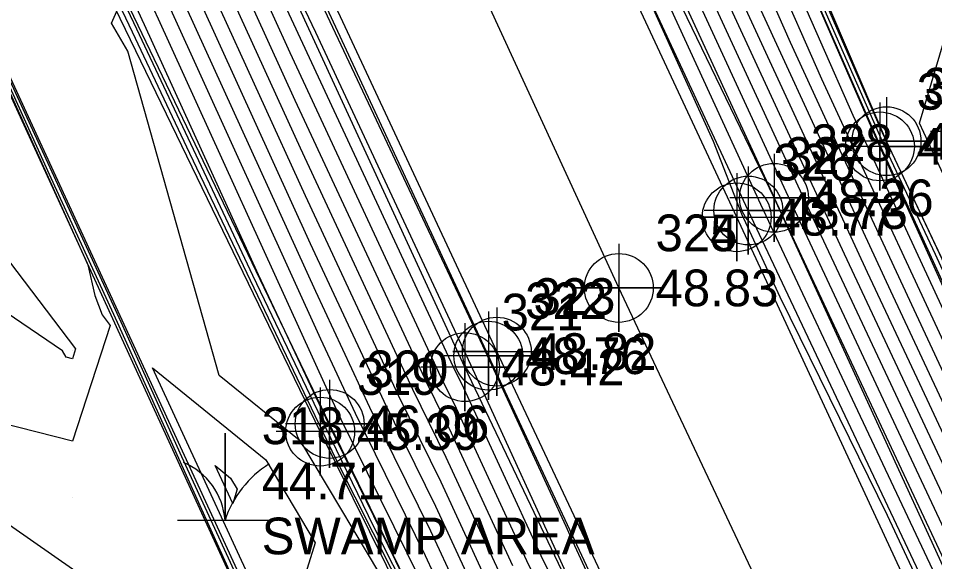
# Model space of a CAD drawing. Extents: x 2090860 to 2091277, y 159470 to 160080.
# Drawn here: x 2090946.3 to 2091008.7, y 159905.6 to 159942.6 of the extents above; entities that cross this region are included whole.
import ezdxf

# ---------------------------------------------------------------- set-up
doc = ezdxf.new("R2010")
doc.units = 0
for name, color, linetype in [('DTM Contours Major', 7, 'Continuous'), ('DTM Contours Minor', 7, 'Continuous'), ('Exist DTM Breakline', 7, 'Continuous'), ('Exist DTM Breakline Cogo Elevation', 7, 'Continuous'), ('Exist DTM Breakline Cogo Number', 7, 'Continuous'), ('Exist DTM Breakline Cogo Point CELL', 7, 'Continuous'), ('Exist DTM Crownline', 7, 'Continuous'), ('Exist DTM Crownline Cogo Elevation', 7, 'Continuous'), ('Exist DTM Crownline Cogo Number', 7, 'Continuous'), ('Exist DTM Crownline Cogo Point CELL', 7, 'Continuous'), ('Exist DTM QL2 LIDAR Elevation Point', 7, 'Continuous'), ('Exist Hydro Swamp or Marsh', 7, 'Continuous'), ('Exist Hydro Swamp or Marsh Cogo Comment', 7, 'Continuous'), ('Exist Hydro Swamp or Marsh Cogo Elevation', 7, 'Continuous'), ('Exist Hydro Swamp or Marsh Cogo Number', 7, 'Continuous'), ('Exist Roads EOP', 7, 'Continuous'), ('Exist Roads EOP Cogo Elevation', 7, 'Continuous'), ('Exist Roads EOP Cogo Number', 7, 'Continuous'), ('Exist Roads EOP Cogo Point CELL', 7, 'Continuous'), ('Exist Roads EOT', 7, 'Continuous'), ('Exist Roads EOT Cogo Elevation', 7, 'Continuous'), ('Exist Roads EOT Cogo Number', 7, 'Continuous'), ('Exist Roads EOT Cogo Point CELL', 7, 'Continuous')]:
    doc.layers.add(name, color=color, linetype=linetype)

msp = doc.modelspace()

# ---------------------------------------------------------------- linework, layer by layer
at = {"layer": 'DTM Contours Major'}
for points in [[(2091021.025, 159898.877), (2091011.639, 159919.455), (2091005.482, 159932.957), (2091005.012, 159933.952), (2090993.094, 159961.193), (2090992.991, 159961.428), (2090991.418, 159965.023), (2090992.968, 159961.452), (2090985.925, 159965.485), (2090984.33, 159968.87), (2090979.616, 159978.837), (2090976.348, 159997.974), (2090975.965, 159998.781), (2090963.783, 160025.207), (2090963.068, 160026.714), (2090951.202, 160052.433), (2090950.873, 160053.127), (2090947.083, 160061.339), (2090947.113, 160061.357)], [(2091021.18, 159890.907), (2091013.639, 159907.174), (2091008.516, 159918.108), (2091005.725, 159924.066), (2091001.855, 159932.408), (2090996.755, 159943.477), (2090989.564, 159959.773), (2090985.428, 159962.142), (2090982.708, 159967.911), (2090974.675, 159984.898), (2090972.744, 159996.202), (2090967.23, 160007.833), (2090960.061, 160023.383), (2090954.323, 160035.484), (2090947.368, 160050.56), (2090945.472, 160054.558), (2090943.253, 160059.365), (2090943.413, 160059.46)], [(2091015.949, 159893.794), (2091005.233, 159916.667), (2090999.394, 159929.129), (2090998.605, 159930.829), (2090988.204, 159953.404), (2090986.126, 159958.114), (2090984.93, 159958.799), (2090981.087, 159966.952), (2090969.734, 159990.958), (2090969.141, 159994.43), (2090958.495, 160016.884), (2090956.34, 160021.56), (2090945.578, 160044.255), (2090943.533, 160048.687), (2090940.07, 160055.988), (2090939.423, 160057.391), (2090939.712, 160057.563)], [(2090915.092, 160045.426), (2090922.919, 160028.827), (2090925.677, 160023.356), (2090935.836, 160001.778), (2090938.587, 159996.284), (2090939.794, 159993.785), (2090945.294, 159982.053), (2090947.597, 159977.284), (2090958.084, 159954.914), (2090958.856, 159953.218), (2090962.481, 159945.429), (2090964.802, 159940.332), (2090975.096, 159918.212), (2090976.136, 159916.102), (2090980.927, 159905.726), (2090983.402, 159900.704)], [(2090910.606, 160043.392), (2090913.448, 160037.366), (2090921.532, 160021.331), (2090926.001, 160011.839), (2090934.731, 159994.403), (2090938.563, 159986.471), (2090941.418, 159980.382), (2090948.738, 159965.223), (2090954.329, 159953.296), (2090956.792, 159947.89), (2090958.683, 159943.825), (2090966.198, 159927.322), (2090971.199, 159916.575), (2090974.729, 159909.419), (2090977.08, 159904.325)], [(2090907.426, 160041.969), (2090911.786, 160032.768), (2090917.984, 160019.602), (2090928.464, 159997.339), (2090930.876, 159992.521), (2090937.332, 159979.157), (2090937.542, 159978.71), (2090949.879, 159953.162), (2090950.574, 159951.679), (2090954.727, 159942.562), (2090954.886, 159942.222), (2090962.638, 159925.196), (2090966.571, 159916.855), (2090967.464, 159914.985), (2090973.015, 159903.605)], [(2090949.577, 159919.577), (2090949.337, 159920), (2090940, 159926.334), (2090935.634, 159930), (2090931.506, 159938.494), (2090937.002, 159940), (2090940.061, 159941.589), (2090940.636, 159939.105), (2090945.228, 159926.717), (2090950.221, 159920.15), (2090950, 159919.471), (2090949.577, 159919.577)], [(2090955.448, 159918.84), (2090963.162, 159912.583), (2090966.529, 159906.939), (2090964.273, 159899.732), (2090955.448, 159918.84)]]:
    msp.add_lwpolyline(points, dxfattribs=at)
at = {"layer": 'DTM Contours Minor'}
for points in [[(2091025.102, 159892.473), (2091012.728, 159918.738), (2091012.329, 159919.613), (2091012.067, 159920.187), (2091005.42, 159934.274), (2091005.163, 159934.86), (2090993.441, 159961.728), (2090992.08, 159964.838), (2090989.382, 159971.02), (2090984.007, 159982.894), (2090977.042, 159998.364), (2090971.588, 160010.408), (2090964.702, 160025.709), (2090959.133, 160037.996), (2090952.362, 160053.053), (2090950.665, 160056.795), (2090948.359, 160061.924), (2090950.641, 160063.035)], [(2091024.64, 159892.328), (2091016.876, 159908.808), (2091011.984, 159919.534), (2091008.774, 159926.572), (2091005.216, 159934.113), (2090999.129, 159948.027), (2090993.216, 159961.578), (2090990.478, 159967.834), (2090989.149, 159970.881), (2090979.664, 159991.834), (2090976.792, 159998.213), (2090966.504, 160020.929), (2090964.429, 160025.539), (2090952.994, 160050.772), (2090952.056, 160052.858), (2090948.153, 160061.461), (2090947.998, 160061.806), (2090948.151, 160061.88)], [(2091023.606, 159891.972), (2091011.906, 159917.209), (2091010.978, 159919.19), (2091010.473, 159920.269), (2091004.292, 159933.592), (2091003.168, 159936.032), (2090992.143, 159961.018), (2090985.801, 159964.649), (2090983.924, 159968.63), (2090978.381, 159980.353), (2090975.447, 159997.531), (2090973.781, 160001.044), (2090962.852, 160024.751), (2090960.882, 160028.906), (2090950.243, 160051.965), (2090949.523, 160053.484), (2090946.126, 160060.846), (2090946.188, 160060.883)], [(2091021.989, 159891.262), (2091013.061, 159910.519), (2091009.337, 159918.469), (2091007.307, 159922.8), (2091002.667, 159932.803), (2090998.893, 159940.995), (2090990.424, 159960.188), (2090985.552, 159962.978), (2090983.114, 159968.151), (2090975.91, 159983.383), (2090973.645, 159996.645), (2090969.414, 160005.57), (2090960.992, 160023.839), (2090956.509, 160033.292), (2090948.326, 160051.028), (2090946.822, 160054.2), (2090944.211, 160059.859), (2090944.338, 160059.934)], [(2091022.798, 159891.617), (2091012.484, 159913.864), (2091010.158, 159918.829), (2091008.89, 159921.535), (2091003.48, 159933.198), (2091001.03, 159938.513), (2090991.283, 159960.603), (2090985.677, 159963.813), (2090983.519, 159968.391), (2090977.145, 159981.868), (2090974.546, 159997.088), (2090971.598, 160003.307), (2090961.922, 160024.295), (2090958.696, 160031.099), (2090949.285, 160051.497), (2090948.173, 160053.842), (2090945.168, 160060.352), (2090945.263, 160060.408)], [(2091014.217, 159903.829), (2091007.695, 159917.748), (2091004.142, 159925.332), (2091001.042, 159932.013), (2090994.617, 159945.959), (2090988.704, 159959.359), (2090985.303, 159961.306), (2090982.303, 159967.671), (2090973.44, 159986.413), (2090971.844, 159995.759), (2090965.046, 160010.096), (2090959.131, 160022.927), (2090952.137, 160037.677), (2090946.409, 160050.092), (2090944.121, 160054.915), (2090942.296, 160058.872), (2090942.487, 160058.986)], [(2091015.372, 159897.139), (2091006.054, 159917.027), (2091000.976, 159927.863), (2090999.417, 159931.224), (2090990.342, 159950.923), (2090986.985, 159958.529), (2090985.054, 159959.635), (2090981.492, 159967.192), (2090970.969, 159989.443), (2090970.042, 159994.873), (2090960.679, 160014.622), (2090957.27, 160022.016), (2090947.764, 160042.063), (2090944.492, 160049.155), (2090941.421, 160055.631), (2090940.381, 160057.885), (2090940.637, 160058.037)], [(2091014.794, 159900.484), (2091006.874, 159917.387), (2091002.559, 159926.597), (2091000.23, 159931.619), (2090992.479, 159948.441), (2090987.845, 159958.944), (2090985.179, 159960.47), (2090981.898, 159967.432), (2090972.204, 159987.928), (2090970.943, 159995.316), (2090962.863, 160012.359), (2090958.2, 160022.472), (2090949.95, 160039.87), (2090945.45, 160049.623), (2090942.771, 160055.273), (2090941.338, 160058.378), (2090941.562, 160058.512)], [(2091016.527, 159890.449), (2091004.412, 159916.306), (2090997.811, 159930.395), (2090997.792, 159930.434), (2090986.066, 159955.886), (2090985.266, 159957.699), (2090984.806, 159957.963), (2090980.682, 159966.713), (2090968.499, 159992.473), (2090968.24, 159993.988), (2090956.311, 160019.147), (2090955.409, 160021.104), (2090943.391, 160046.448), (2090942.575, 160048.218), (2090938.72, 160056.346), (2090938.465, 160056.898), (2090938.787, 160057.089)], [(2091015.092, 159888.281), (2091005.494, 159908.792), (2091002.253, 159915.399), (2090998.196, 159923.671), (2090995.587, 159929.309), (2090993.655, 159934.254), (2090987.577, 159947.689), (2090983.614, 159956.284), (2090983.391, 159956.773), (2090979.397, 159965.44), (2090979.189, 159965.897), (2090967.415, 159991.324), (2090966.567, 159993.113), (2090960.639, 160005.911), (2090959.796, 160007.69), (2090947.752, 160033.198), (2090947.057, 160034.665), (2090937.109, 160055.735), (2090936.921, 160056.131), (2090936.936, 160056.14)], [(2091009.719, 159902.684), (2091003.488, 159915.918), (2091000.285, 159922.734), (2090996.873, 159929.981), (2090990.78, 159943.197), (2090984.364, 159957.258), (2090983.277, 159959.617), (2090980.176, 159966.423), (2090978.448, 159970.155), (2090967.363, 159993.547), (2090966.269, 159995.909), (2090955.847, 160017.91), (2090953.21, 160023.496), (2090943.221, 160044.585), (2090940.726, 160049.87), (2090937.604, 160056.462), (2090937.861, 160056.615)], [(2090918.443, 160047.072), (2090925.071, 160032.691), (2090928.75, 160024.871), (2090936.833, 160007.361), (2090941.384, 159997.661), (2090946.344, 159987.242), (2090948.128, 159983.436), (2090958.851, 159960.931), (2090960.998, 159956.352), (2090964.881, 159948.099), (2090965.492, 159946.787), (2090977.739, 159920.762), (2090978.261, 159919.644), (2090983.592, 159908.064), (2090984.057, 159907.047), (2090994.33, 159884.723)], [(2090917.335, 160046.443), (2090927.654, 160024.558), (2090927.75, 160024.369), (2090931.7, 160015.979), (2090940.501, 159997.22), (2090941.185, 159995.783), (2090947.222, 159982.907), (2090948.733, 159979.736), (2090959.976, 159955.756), (2090960.546, 159954.544), (2090964.408, 159946.258), (2090966.553, 159941.699), (2090977.104, 159919.081), (2090978.421, 159916.221), (2090982.884, 159906.464), (2090984.288, 159903.411)], [(2090916.214, 160045.934), (2090925.287, 160026.693), (2090926.714, 160023.863), (2090938.295, 159999.263), (2090939.55, 159996.755), (2090940.102, 159995.614), (2090946.263, 159982.47), (2090947.312, 159980.299), (2090959.023, 159955.318), (2090959.373, 159954.55), (2090963.43, 159945.83), (2090964.452, 159943.584), (2090976.07, 159918.621), (2090976.488, 159917.773), (2090981.889, 159906.077), (2090983.02, 159903.782)], [(2090913.971, 160044.918), (2090920.551, 160030.962), (2090924.641, 160022.85), (2090933.377, 160004.293), (2090937.623, 159995.814), (2090939.486, 159991.957), (2090944.325, 159981.635), (2090947.882, 159974.268), (2090957.145, 159954.509), (2090958.34, 159951.886), (2090961.531, 159945.028), (2090965.151, 159937.08), (2090974.122, 159917.803), (2090975.785, 159914.432), (2090979.965, 159905.376)], [(2090912.849, 160044.409), (2090918.183, 160033.097), (2090923.605, 160022.344), (2090930.919, 160006.809), (2090936.659, 159995.344), (2090939.178, 159990.128), (2090943.356, 159981.217), (2090948.168, 159971.253), (2090956.207, 159954.105), (2090957.824, 159950.554), (2090960.582, 159944.627), (2090965.5, 159933.827), (2090973.148, 159917.393), (2090975.433, 159912.761), (2090979.004, 159905.026)], [(2090911.728, 160043.901), (2090915.815, 160035.231), (2090922.569, 160021.838), (2090928.46, 160009.324), (2090935.695, 159994.873), (2090938.871, 159988.3), (2090942.387, 159980.799), (2090948.453, 159968.238), (2090955.268, 159953.701), (2090957.308, 159949.222), (2090959.632, 159944.226), (2090965.849, 159930.575), (2090972.174, 159916.984), (2090975.081, 159911.09), (2090978.042, 159904.675)], [(2090908.363, 160042.375), (2090908.712, 160041.635), (2090919.46, 160020.319), (2090921.084, 160016.87), (2090932.804, 159993.462), (2090937.948, 159982.814), (2090939.48, 159979.546), (2090949.308, 159959.192), (2090952.452, 159952.487), (2090955.76, 159945.226), (2090956.784, 159943.023), (2090966.896, 159920.817), (2090969.251, 159915.756), (2090974.025, 159906.078), (2090975.157, 159903.624)], [(2090909.485, 160042.884), (2090911.08, 160039.501), (2090920.496, 160020.825), (2090923.543, 160014.354), (2090933.768, 159993.933), (2090938.255, 159984.643), (2090940.449, 159979.964), (2090949.023, 159962.207), (2090953.39, 159952.892), (2090956.276, 159946.558), (2090957.734, 159943.424), (2090966.547, 159924.07), (2090970.225, 159916.166), (2090974.377, 159907.749), (2090976.119, 159903.975)], [(2090907.064, 160041.816), (2090913.959, 160027.266), (2090917.643, 160019.44), (2090925.862, 160001.979), (2090930.45, 159992.315), (2090932.739, 159987.48), (2090936.984, 159978.555), (2090940.085, 159972.01), (2090949.879, 159951.423), (2090950.719, 159949.661), (2090954.36, 159941.937), (2090962.272, 159925.16), (2090967.223, 159914.789), (2090970.51, 159908.05), (2090973.119, 159902.868)], [(2090907.788, 160042.123), (2090909.613, 160038.271), (2090916.596, 160023.437), (2090918.424, 160019.813), (2090918.625, 160019.385), (2090931.84, 159992.992), (2090937.64, 159980.985), (2090938.511, 159979.128), (2090949.594, 159956.177), (2090951.513, 159952.083), (2090955.244, 159943.894), (2090955.835, 159942.622), (2090967.245, 159917.565), (2090968.277, 159915.347), (2090973.673, 159904.407)], [(2090906.701, 160041.663), (2090916.132, 160021.763), (2090917.301, 160019.278), (2090919.911, 160013.734), (2090930.148, 159992.169), (2090935.256, 159981.379), (2090936.616, 159978.521), (2090944.254, 159962.401), (2090949.505, 159951.363), (2090952.287, 159945.521), (2090954.079, 159941.72), (2090957.972, 159933.464), (2090966.981, 159914.593), (2090968.004, 159912.496), (2090972.898, 159902.775)], [(2090898.298, 160040.07), (2090902.561, 160030.534), (2090909.741, 160015.052), (2090910.823, 160012.853), (2090918.991, 159995.373), (2090922.033, 159989.405), (2090928.025, 159976.37), (2090934.637, 159962.164), (2090937.707, 159955.499), (2090940.625, 159949.227), (2090948.523, 159931.794), (2090953.056, 159921.956), (2090965.045, 159895.337)], [(2091012.106, 159925.968), (2091007.685, 159935.502), (2091010.132, 159943.75), (2090994.374, 159961.259), (2090993.699, 159961.981), (2090993.523, 159962.203), (2090989.615, 159971.158), (2090988.349, 159973.954), (2090977.292, 159998.516), (2090976.671, 159999.886), (2090968.466, 160018.121), (2090977.233, 160001.212), (2090985.269, 159999.581), (2090977.053, 160017.74)], [(2090923.078, 159986.602), (2090934.563, 159961.929), (2090935.674, 159959.518), (2090940.467, 159949.216), (2090951.052, 159925.852), (2090951.531, 159923.784), (2090952.026, 159922.449), (2090952.564, 159921.741), (2090950, 159913.865), (2090945.097, 159915.097), (2090942.31, 159920), (2090940, 159921.567), (2090930.226, 159929.774), (2090937.638, 159920), (2090930, 159911.339), (2090928.613, 159910), (2090928.694, 159908.694), (2090930, 159907.169), (2090932.034, 159900)], [(2090971.838, 159903.298), (2090965.559, 159913.825), (2090960.005, 159918.329), (2090953.785, 159940.417), (2090952.656, 159942.311), (2090953.018, 159943.141), (2090949.131, 159951.303), (2090948.423, 159952.793), (2090946.196, 159957.493), (2090935.425, 159968.942), (2090923.729, 159986.244), (2090932.971, 159966.138), (2090934.711, 159962.399), (2090939.74, 159951.48), (2090940.783, 159949.239), (2090943.605, 159943.01), (2090953.294, 159921.983), (2090957.425, 159912.812), (2090965.766, 159894.719)], [(2090959.724, 159912.186), (2090960.765, 159911.342), (2090961.219, 159910.58), (2090960.915, 159909.607), (2090959.724, 159912.186)], [(2090940, 159891.292), (2090936.919, 159900), (2090935.698, 159904.302), (2090938.586, 159910), (2090940, 159911.701), (2090940.616, 159910.616), (2090943.071, 159910), (2090950, 159905.156), (2090963.729, 159895.221), (2090953.729, 159896.271), (2090950, 159897.832), (2090943.458, 159896.542), (2090940, 159891.292)]]:
    msp.add_lwpolyline(points, dxfattribs=at)
at = {"layer": 'Exist DTM Breakline'}
for points in [[(2091060.143, 159819.743), (2091040.416, 159857.574), (2091023.862, 159892.084), (2091004.981, 159933.927), (2090988.922, 159970.746), (2090947.972, 160061.797)], [(2091061.634, 159820.633), (2091041.562, 159858.316), (2091025.181, 159892.498), (2091005.429, 159934.281), (2090989.687, 159971.201), (2090948.616, 160062.008)], [(2091054.851, 159814.302), (2091016.781, 159888.977), (2090997.773, 159930.425), (2090980.346, 159966.514), (2090937.845, 160056.578)], [(2091012.481, 159842.709), (2090995.611, 159879.293), (2090976.725, 159918.896), (2090959.8, 159955.653), (2090940.36, 159997.15), (2090917.627, 160046.575)], [(2091019.809, 159801.913), (2091004.418, 159836.946), (2090986.475, 159875.987), (2090967.517, 159915.028), (2090950.041, 159951.449), (2090930.695, 159992.433), (2090908.049, 160042.233)], [(2091019.111, 159801.55), (2091003.076, 159836.513), (2090986.016, 159875.809), (2090966.872, 159914.505), (2090949.073, 159951.294), (2090930.109, 159992.15), (2090906.432, 160041.549)], [(2090898.02, 160040.012), (2090922.126, 159989.703), (2090940.871, 159949.246), (2090967.299, 159891.857)], [(2090895.734, 160038.669), (2090921.911, 159989.017), (2090940.353, 159949.207), (2090966.689, 159891.716)]]:
    msp.add_lwpolyline(points, dxfattribs=at)
at = {"layer": 'Exist DTM Breakline Cogo Point CELL'}
for points in [[(2091004.981, 159936.927), (2091004.981, 159930.927), (2091004.981, 159933.927), (2091007.981, 159933.927), (2091001.981, 159933.927)], [(2091005.429, 159937.281), (2091005.429, 159931.281), (2091005.429, 159934.281), (2091008.429, 159934.281), (2091002.429, 159934.281)], [(2090997.773, 159933.425), (2090997.773, 159927.425), (2090997.773, 159930.425), (2091000.773, 159930.425), (2090994.773, 159930.425)], [(2090976.725, 159921.896), (2090976.725, 159915.896), (2090976.725, 159918.896), (2090979.725, 159918.896), (2090973.725, 159918.896)], [(2090967.517, 159918.028), (2090967.517, 159912.028), (2090967.517, 159915.028), (2090970.517, 159915.028), (2090964.517, 159915.028)], [(2090966.872, 159917.505), (2090966.872, 159911.505), (2090966.872, 159914.505), (2090969.872, 159914.505), (2090963.872, 159914.505)]]:
    msp.add_lwpolyline(points, dxfattribs=at)
for centre in [(2091005.429, 159934.281), (2091004.981, 159933.927), (2090997.773, 159930.425), (2090976.725, 159918.896), (2090967.517, 159915.028), (2090966.872, 159914.505)]:
    msp.add_circle(centre, 2.344, dxfattribs=at)
at = {"layer": 'Exist DTM Crownline'}
msp.add_lwpolyline([(2091041.896, 159807.58), (2091022.738, 159848.476), (2091006.16, 159884.052), (2090987.202, 159924.29), (2090970.349, 159960.929), (2090951.234, 160001.943), (2090928.333, 160051.748)], dxfattribs=at)
at = {"layer": 'Exist DTM Crownline Cogo Point CELL'}
msp.add_lwpolyline([(2090987.202, 159927.29), (2090987.202, 159921.29), (2090987.202, 159924.29), (2090990.202, 159924.29), (2090984.202, 159924.29)], dxfattribs=at)
msp.add_circle((2090987.202, 159924.29), 2.344, dxfattribs=at)
at = {"layer": 'Exist DTM QL2 LIDAR Elevation Point'}
for p, q in [((2090950, 159920), (2090950, 159920)), ((2090950, 159910), (2090950, 159910))]:
    msp.add_line(p, q, dxfattribs=at)
at = {"layer": 'Exist Hydro Swamp or Marsh'}
msp.add_line((2090960.391, 159911.148), (2090960.391, 159911.148), dxfattribs=at)
for points in [[(2091008.415, 159934.969), (2091011.641, 159934.969), (2091011.641, 159940.886), (2091011.641, 159934.969), (2091014.866, 159934.969)], [(2090957.166, 159908.474), (2090960.392, 159908.474), (2090960.392, 159914.391), (2090960.392, 159908.474), (2090963.617, 159908.474)]]:
    msp.add_lwpolyline(points, dxfattribs=at)
for centre, radius, start, end in [((2090955.792, 159908.141), 4.612, 4.14034, 67.53497), ((2090967.233, 159906.201), 7.208, 122.12745, 161.62219)]:
    msp.add_arc(centre, radius, start, end, dxfattribs=at)
at = {"layer": 'Exist Roads EOP'}
for points in [[(2091050.887, 159811.953), (2091031.567, 159853.358), (2091015.44, 159888.433), (2090996.018, 159929.558), (2090979.118, 159965.859), (2090960.144, 160006.791), (2090936.877, 160056.11)], [(2091032.873, 159803.467), (2091013.956, 159843.468), (2090996.901, 159879.939), (2090978.321, 159919.673), (2090961.239, 159956.493), (2090941.84, 159997.888), (2090918.792, 160047.284)]]:
    msp.add_lwpolyline(points, dxfattribs=at)
at = {"layer": 'Exist Roads EOP Cogo Point CELL'}
for points in [[(2090996.018, 159932.558), (2090996.018, 159926.558), (2090996.018, 159929.558), (2090999.018, 159929.558), (2090993.018, 159929.558)], [(2090978.321, 159922.673), (2090978.321, 159916.673), (2090978.321, 159919.673), (2090981.321, 159919.673), (2090975.321, 159919.673)]]:
    msp.add_lwpolyline(points, dxfattribs=at)
for centre in [(2090996.018, 159929.558), (2090978.321, 159919.673)]:
    msp.add_circle(centre, 2.344, dxfattribs=at)
at = {"layer": 'Exist Roads EOT'}
for points in [[(2091050.358, 159811.619), (2091030.997, 159852.885), (2091014.318, 159887.944), (2090995.228, 159929.102), (2090978.274, 159965.509), (2090959.414, 160006.451), (2090936.296, 160055.791)], [(2091033.429, 159803.706), (2091014.624, 159843.758), (2090997.608, 159880.208), (2090978.895, 159919.952), (2090961.789, 159956.632), (2090942.516, 159998.302), (2090919.608, 160047.643)]]:
    msp.add_lwpolyline(points, dxfattribs=at)
at = {"layer": 'Exist Roads EOT Cogo Point CELL'}
for points in [[(2090995.228, 159932.102), (2090995.228, 159926.102), (2090995.228, 159929.102), (2090992.228, 159929.102), (2090998.228, 159929.102)], [(2090987.202, 159927.29), (2090987.202, 159921.29), (2090987.202, 159924.29), (2090984.202, 159924.29), (2090990.202, 159924.29)], [(2090978.895, 159922.952), (2090978.895, 159916.952), (2090978.895, 159919.952), (2090975.895, 159919.952), (2090981.895, 159919.952)]]:
    msp.add_lwpolyline(points, dxfattribs=at)
for centre in [(2090995.228, 159929.102), (2090987.202, 159924.29), (2090978.895, 159919.952)]:
    msp.add_circle(centre, 2.344, dxfattribs=at)

# ---------------------------------------------------------------- texts
at = {"layer": 'Exist DTM Breakline Cogo Elevation'}
for s, p in [('46.04', (2091007.481, 159932.677)), ('45.49', (2091007.929, 159933.031)), ('48.26', (2091000.273, 159929.175)), ('48.42', (2090979.225, 159917.646)), ('45.39', (2090969.372, 159913.255)), ('46.06', (2090970.017, 159913.778))]:
    msp.add_text(s, height=2.5, dxfattribs=at).set_placement(p)
at = {"layer": 'Exist DTM Breakline Cogo Number'}
for s, p in [('329', (2091007.481, 159936.427)), ('330', (2091007.929, 159936.781)), ('328', (2091000.273, 159932.925)), ('321', (2090979.225, 159921.396)), ('319', (2090969.372, 159917.005)), ('320', (2090970.017, 159917.528))]:
    msp.add_text(s, height=2.5, dxfattribs=at).set_placement(p)
at = {"layer": 'Exist DTM Crownline Cogo Elevation'}
msp.add_text('48.83', height=2.5, dxfattribs=at).set_placement((2090989.702, 159923.04))
at = {"layer": 'Exist DTM Crownline Cogo Number'}
msp.add_text('325', height=2.5, dxfattribs=at).set_placement((2090989.702, 159926.79))
at = {"layer": 'Exist Hydro Swamp or Marsh Cogo Comment'}
msp.add_text('SWAMP AREA', height=2.5, dxfattribs=at).set_placement((2090962.891, 159906.148))
at = {"layer": 'Exist Hydro Swamp or Marsh Cogo Elevation'}
msp.add_text('44.71', height=2.5, dxfattribs=at).set_placement((2090962.891, 159909.898))
at = {"layer": 'Exist Hydro Swamp or Marsh Cogo Number'}
msp.add_text('318', height=2.5, dxfattribs=at).set_placement((2090962.891, 159913.648))
at = {"layer": 'Exist Roads EOP Cogo Elevation'}
for s, p in [('48.73', (2090998.518, 159928.308)), ('48.76', (2090980.821, 159918.423))]:
    msp.add_text(s, height=2.5, dxfattribs=at).set_placement(p)
at = {"layer": 'Exist Roads EOP Cogo Number'}
for s, p in [('327', (2090998.518, 159932.058)), ('322', (2090980.821, 159922.173))]:
    msp.add_text(s, height=2.5, dxfattribs=at).set_placement(p)
at = {"layer": 'Exist Roads EOT Cogo Elevation'}
for s, p in [('48.77', (2090997.728, 159927.852)), ('48.83', (2090989.702, 159923.04)), ('48.82', (2090981.395, 159918.702))]:
    msp.add_text(s, height=2.5, dxfattribs=at).set_placement(p)
at = {"layer": 'Exist Roads EOT Cogo Number'}
for s, p in [('326', (2090997.728, 159931.602)), ('324', (2090989.702, 159926.79)), ('323', (2090981.395, 159922.452))]:
    msp.add_text(s, height=2.5, dxfattribs=at).set_placement(p)

doc.saveas('drawing.dxf')
